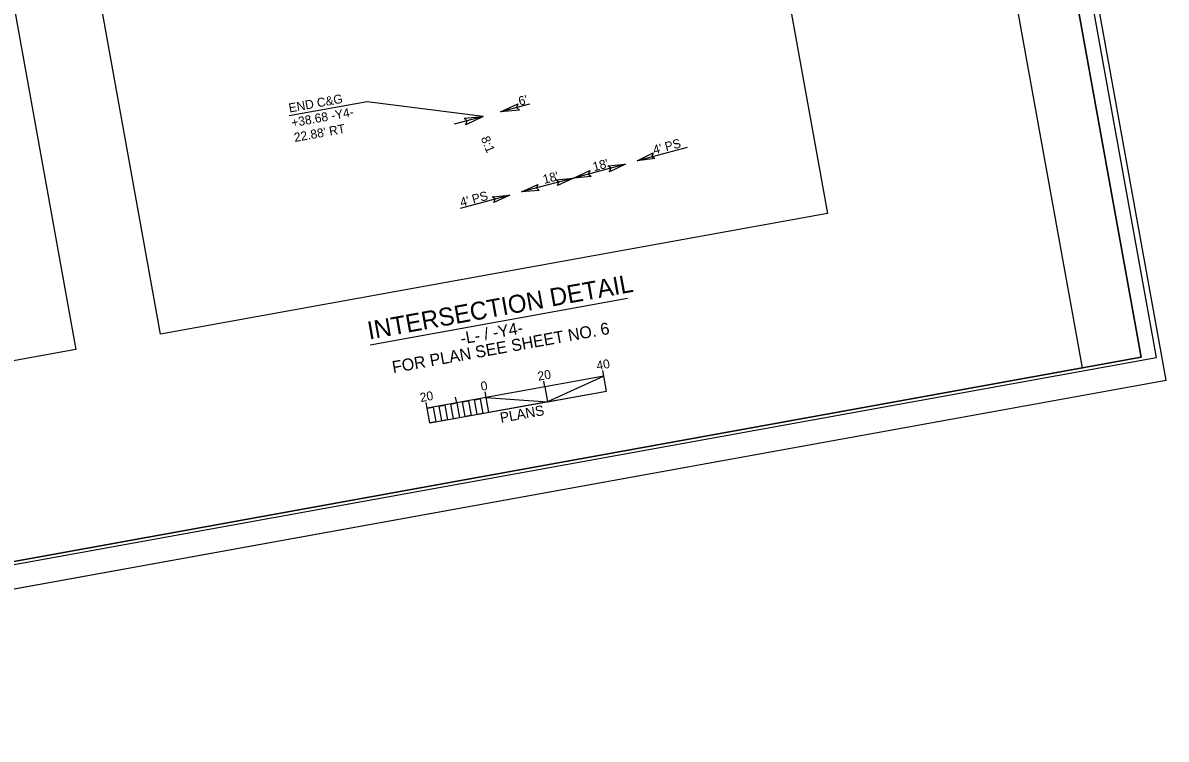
# Model space of a CAD drawing. Extents: x 1620721 to 1621526, y 897852 to 898403.
# Drawn here: x 1621079.6 to 1621461.8, y 897851.9 to 898091.1 of the extents above; entities that cross this region are included whole.
import ezdxf

# ---------------------------------------------------------------- set-up
doc = ezdxf.new("R2010")
doc.units = 0
for name, color, linetype in [('Default', 7, 'Continuous'), ('Prop Conc 2ft 6in Curb and Gutter', 7, 'Continuous'), ('Prop Dimension', 7, 'Continuous'), ('Prop DSN Text', 7, 'Continuous'), ('Prop Terminator CELL', 7, 'Continuous'), ('Sheet Clip Boundary CELL', 7, 'Continuous'), ('Sheet Cutting Line CELL', 7, 'Continuous'), ('Sheet Data Field CELL', 7, 'Continuous'), ('Sheet Layout Plan Border', 7, 'Continuous'), ('Sheet Plan CELL', 7, 'Continuous'), ('Sheet Plot Border Inside CELL', 7, 'Continuous'), ('Sheet Plot Border Outside CELL', 7, 'Continuous'), ('Sheet Title CELL', 7, 'Continuous')]:
    doc.layers.add(name, color=color, linetype=linetype)

msp = doc.modelspace()

# ---------------------------------------------------------------- linework, layer by layer
at = {"layer": 'Default'}
msp.add_line((1621195.68, 897983.59), (1621281.79, 897999.17), dxfattribs=at)
at = {"layer": 'Prop Conc 2ft 6in Curb and Gutter'}
for p, q in [((1621194.69, 898064.77), (1621168.65, 898060.06)), ((1621233.5, 898059.82), (1621194.69, 898064.77))]:
    msp.add_line(p, q, dxfattribs=at)
at = {"layer": 'Prop Dimension'}
for p, q in [((1621248.96, 898063.96), (1621239.3, 898061.38)), ((1621233.5, 898059.82), (1621223.84, 898057.24)), ((1621301.66, 898049.53), (1621284.94, 898045.06)), ((1621281.11, 898043.92), (1621263.72, 898039.28)), ((1621263.72, 898039.28), (1621246.33, 898034.63)), ((1621242.46, 898033.6), (1621225.75, 898029.13))]:
    msp.add_line(p, q, dxfattribs=at)
at = {"layer": 'Prop DSN Text'}
for points in [[(1621069.41, 898297.84), (1621292.41, 898338.21), (1621348.65, 898027.48), (1621125.66, 897987.11)], [(1620818.11, 898252.36), (1621041.11, 898292.72), (1621097.35, 897981.99), (1620874.36, 897941.62)]]:
    msp.add_lwpolyline(points, close=True, dxfattribs=at)
at = {"layer": 'Prop Terminator CELL'}
for points in [[(1621245.66, 898061.96), (1621239.3, 898061.38), (1621245.13, 898064.1), (1621244.64, 898062.81)], [(1621227.13, 898059.24), (1621233.5, 898059.82), (1621227.67, 898057.1), (1621228.15, 898058.39)], [(1621290.84, 898045.77), (1621284.94, 898045.06), (1621290.28, 898047.74), (1621289.86, 898046.53)], [(1621275.2, 898043.38), (1621281.11, 898043.92), (1621275.69, 898041.4), (1621276.15, 898042.6)], [(1621257.81, 898038.74), (1621263.72, 898039.28), (1621258.3, 898036.75), (1621258.76, 898037.95)], [(1621269.63, 898039.81), (1621263.72, 898039.28), (1621269.13, 898041.8), (1621268.68, 898040.6)], [(1621252.24, 898035.17), (1621246.33, 898034.63), (1621251.74, 898037.15), (1621251.29, 898035.96)], [(1621236.55, 898033.06), (1621242.46, 898033.6), (1621237.05, 898031.08), (1621237.5, 898032.27)]]:
    msp.add_lwpolyline(points, close=True, dxfattribs=at)
at = {"layer": 'Sheet Clip Boundary CELL'}
msp.add_lwpolyline([(1620882.81, 897876.15), (1621433.86, 897975.9), (1621374.12, 898305.94), (1621299.62, 898292.45), (1621284.56, 898375.7), (1620808, 898289.43)], close=True, dxfattribs=at)
at = {"layer": 'Sheet Cutting Line CELL'}
msp.add_line((1620799.2, 897851.87), (1621461.84, 897971.81), dxfattribs=at)
at = {"layer": 'Sheet Data Field CELL'}
msp.add_line((1621254.16, 897969.51), (1621253.81, 897971.47), dxfattribs=at)
at = {"layer": 'Sheet Layout Plan Border'}
msp.add_lwpolyline([(1620882.81, 897876.15), (1621433.86, 897975.9), (1621374.12, 898305.94), (1621299.62, 898292.45), (1621284.56, 898375.7), (1620808, 898289.43)], close=True, dxfattribs=at)
at = {"layer": 'Sheet Plan CELL'}
for points in [[(1621378.74, 898392.74), (1620788.32, 898285.87), (1620863.13, 897872.59), (1621453.54, 897979.46)], [(1620863.13, 897872.59), (1620788.31, 898285.86), (1621299.99, 898378.49), (1621310.69, 898319.43), (1621389.42, 898333.68), (1621453.54, 897979.46)]]:
    msp.add_lwpolyline(points, close=True, dxfattribs=at)
at = {"layer": 'Sheet Plot Border Inside CELL'}
msp.add_lwpolyline([(1620802.89, 897860.66), (1621458.63, 897979.36), (1621383.47, 898394.61), (1620727.73, 898275.92)], close=True, dxfattribs=at)
at = {"layer": 'Sheet Plot Border Outside CELL'}
msp.add_lwpolyline([(1620799.2, 897851.87), (1621461.84, 897971.81), (1621383.82, 898402.8), (1620721.19, 898282.86)], close=True, dxfattribs=at)
at = {"layer": 'Sheet Title CELL'}
for p, q in [((1621273.84, 897973.06), (1621273.48, 897975.03)), ((1621273.84, 897973.06), (1621214.8, 897962.38)), ((1621254.16, 897969.5), (1621253.8, 897971.47)), ((1621215.69, 897957.46), (1621274.73, 897968.14)), ((1621224.64, 897964.15), (1621224.28, 897966.13)), ((1621234.48, 897965.94), (1621234.12, 897967.9)), ((1621254.16, 897969.5), (1621255.05, 897964.58)), ((1621214.8, 897962.38), (1621214.44, 897964.34))]:
    msp.add_line(p, q, dxfattribs=at)
for points in [[(1621273.84, 897973.06), (1621255.05, 897964.58), (1621274.73, 897968.14)], [(1621214.8, 897962.38), (1621216.77, 897962.73), (1621217.66, 897957.81), (1621215.69, 897957.46)], [(1621218.73, 897963.09), (1621220.7, 897963.44), (1621221.59, 897958.52), (1621219.63, 897958.17)], [(1621222.67, 897963.8), (1621224.64, 897964.15), (1621225.53, 897959.24), (1621223.56, 897958.88)], [(1621226.61, 897964.51), (1621228.57, 897964.87), (1621229.46, 897959.95), (1621227.5, 897959.6)], [(1621230.54, 897965.23), (1621232.51, 897965.58), (1621233.4, 897960.66), (1621231.43, 897960.31)], [(1621234.48, 897965.94), (1621255.05, 897964.58), (1621235.37, 897961.02)]]:
    msp.add_lwpolyline(points, close=True, dxfattribs=at)

# ---------------------------------------------------------------- texts
at = {"layer": 'Default'}
for s, height, p in [('INTERSECTION DETAIL', 6, (1621195.38, 897985.3)), ('FOR PLAN SEE SHEET NO. 6', 4, (1621203.44, 897974.09)), ('-L- / -Y4-', 4, (1621226.26, 897983.67))]:
    msp.add_text(s, height=height, rotation=10.2599, dxfattribs=at).set_placement(p)
at = {"layer": 'Prop Conc 2ft 6in Curb and Gutter'}
for s, p in [('END C&G', (1621168.76, 898061.16)), ('+38.68 -Y4-', (1621169.65, 898056.24)), ("22.88' RT", (1621170.54, 898051.32))]:
    msp.add_text(s, height=3, rotation=10.2599, dxfattribs=at).set_placement(p)
at = {"layer": 'Prop Dimension'}
for s, rotation, p in [("6'", 14.9833, (1621245.74, 898063.42)), ('8:1', 292.11, (1621232.66, 898052.57)), ("4' PS", 14.9555, (1621290.71, 898047.16)), ("18'", 14.9555, (1621270.58, 898041.51)), ("18'", 14.9555, (1621253.9, 898037.29)), ("4' PS", 14.9555, (1621226.21, 898029.65))]:
    msp.add_text(s, height=3, rotation=rotation, dxfattribs=at).set_placement(p)
at = {"layer": 'Sheet Data Field CELL'}
for s, p in [('40', (1621271.66, 897975.11)), ('20', (1621251.98, 897971.55)), ('20', (1621212.62, 897964.42))]:
    msp.add_text(s, height=3, rotation=10.2599, dxfattribs=at).set_placement(p)
at = {"layer": 'Sheet Title CELL'}
for s, height, p in [('0', 3, (1621232.96, 897968.16)), ('PLANS', 3.4, (1621239.46, 897957.49))]:
    msp.add_text(s, height=height, rotation=10.2599, dxfattribs=at).set_placement(p)

doc.saveas('drawing.dxf')
